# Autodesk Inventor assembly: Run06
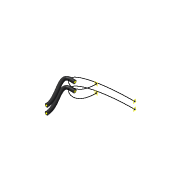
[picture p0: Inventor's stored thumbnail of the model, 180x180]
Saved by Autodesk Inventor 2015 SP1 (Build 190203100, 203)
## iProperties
Created: 2013-02
Part Number: Run06
Document SubType Name: Assembly
Designer: Marci
Author: Marci
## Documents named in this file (3)
- C:\Users\TREINA11\Desktop\#01- Polymechanics and Automation\01 - 3D Models\Pneumatic System\Teljes hajtás.Run07.iam
- C:\Users\TREINA11\Desktop\#01- Polymechanics and Automation\01 - 3D Models\Pneumatic System\Teljes hajtás.Hose03.iam
- C:\Users\TREINA11\Desktop\#01- Polymechanics and Automation\01 - 3D Models\Pneumatic System\Teljes hajtás.Hose04.iam
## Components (2 placed, 2 different names)
1. Flexible Hose 03 [sub-assembly]
2. Flexible Hose 04 [sub-assembly]
